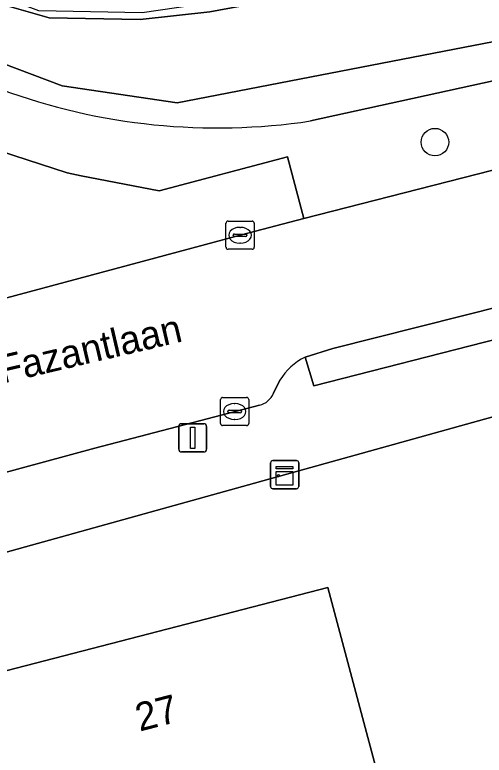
# Model space of a CAD drawing. Extents: x 161772 to 163126, y 383092 to 383917.
# Drawn here: x 161980.53 to 161997.2, y 383449.11 to 383475.41 of the extents above; entities that cross this region are included whole.
import ezdxf

# ---------------------------------------------------------------- set-up
doc = ezdxf.new("R2010")
doc.units = 0
for name, color, linetype in [('IMGEO_Boom', 7, 'Continuous'), ('IMGEO_Erf', 7, 'Continuous'), ('IMGEO_Groenvoorziening', 7, 'Continuous'), ('IMGEO_Kast', 7, 'Continuous'), ('IMGEO_Kolk', 7, 'Continuous'), ('IMGEO_Lichtmast', 7, 'Continuous'), ('IMGEO_Oever', 7, 'Continuous'), ('IMGEO_Openbare_ruimte_label', 7, 'Continuous'), ('IMGEO_Pand', 7, 'Continuous'), ('IMGEO_Pand_nummerreeks', 7, 'Continuous'), ('IMGEO_Rijbaan_lokaal_gesloten', 7, 'Continuous'), ('IMGEO_Voetpad_gesloten', 7, 'Continuous'), ('IMGEO_Voetpad_open', 7, 'Continuous'), ('IMGEO_Waterloop', 7, 'Continuous')]:
    doc.layers.add(name, color=color, linetype=linetype)

msp = doc.modelspace()

# ---------------------------------------------------------------- linework, layer by layer
at = {"layer": 'IMGEO_Boom'}
msp.add_circle((161995.452, 383470.891), 0.489, dxfattribs=at)
at = {"layer": 'IMGEO_Erf'}
msp.add_lwpolyline([(162013.474, 383465.049), (162000.265, 383462.051), (162000.295, 383461.907), (161996.785, 383460.931), (161992.404, 383459.714), (161973.318, 383454.411), (161972.09, 383452.564), (161979.364, 383425.078), (161979.14, 383425.031), (161985.923, 383398.52), (161987.571, 383390.708)], dxfattribs=at)
msp.add_lwpolyline([(161984.667, 383430.279), (161984.004, 383430.663), (161982.385, 383436.719), (161981.739, 383439.133), (161980.721, 383438.861), (161979.488, 383439.574), (161978.579, 383442.975), (161977.67, 383446.373), (161978.28, 383447.427), (161979.282, 383447.695), (161978.237, 383451.598), (161991.651, 383455.067), (161992.979, 383450.097), (161993.795, 383447.047), (161990.987, 383446.296), (161991.115, 383445.818), (161991.983, 383442.57), (161993.405, 383442.951), (161994.309, 383439.636), (161996.032, 383433.317), (161989.498, 383431.57)], close=True, dxfattribs=at)
at = {"layer": 'IMGEO_Groenvoorziening'}
for points in [[(162031.7, 383476.189), (162040.283, 383477.247), (162056.048, 383479.111), (162056.772, 383479.174), (162056.543, 383481.404), (162057.145, 383481.468), (162057.113, 383481.8), (162057.695, 383483.305), (162056.342, 383483.117), (162028.627, 383479.262), (162018.222, 383477.318), (162000, 383473.614), (161991.036, 383471.642)], [(161977.609, 383471.347), (161982.392, 383469.803), (161982.884, 383469.691), (161985.654, 383469.166), (161990.219, 383470.372), (161990.801, 383468.172), (162000, 383470.537), (162011.434, 383473.114)]]:
    msp.add_lwpolyline(points, dxfattribs=at)
msp.add_arc((161987.728, 383493.685), 22.29, 249.8312, 278.534, dxfattribs=at)
at = {"layer": 'IMGEO_Kast'}
for p, q in [((161989.69, 383459.579), (161990.531, 383459.579)), ((161990.531, 383459.579), (161989.69, 383459.579)), ((161989.615, 383458.654), (161989.615, 383459.495)), ((161989.615, 383459.495), (161989.615, 383458.654)), ((161990.615, 383459.504), (161990.615, 383458.663)), ((161990.615, 383458.663), (161990.615, 383459.504)), ((161990.54, 383458.579), (161989.699, 383458.579)), ((161989.699, 383458.579), (161990.54, 383458.579))]:
    msp.add_line(p, q, dxfattribs=at)
for points in [[(161989.81, 383459.369), (161990.41, 383459.369), (161990.41, 383459.284), (161989.81, 383459.284), (161989.81, 383459.369)], [(161989.81, 383459.194), (161990.41, 383459.194), (161990.41, 383458.705), (161989.81, 383458.705), (161989.81, 383459.194)]]:
    msp.add_lwpolyline(points, dxfattribs=at)
msp.add_circle((161989.894, 383459.043), 0.0377, dxfattribs=at)
for centre, start, end in [((161989.693, 383459.501), 92.4484, 184.2845), ((161989.693, 383459.501), 92.4484, 184.2845), ((161990.537, 383459.501), 2.4484, 94.2845), ((161990.537, 383459.501), 2.4484, 94.2845), ((161989.693, 383458.657), 182.4484, 274.2845), ((161989.693, 383458.657), 182.4484, 274.2845), ((161990.537, 383458.657), 272.4484, 4.2845), ((161990.537, 383458.657), 272.4484, 4.2845)]:
    msp.add_arc(centre, 0.0779, start, end, dxfattribs=at)
at = {"layer": 'IMGEO_Kolk'}
for p, q in [((161988.031, 383467.158), (161988.031, 383468.01)), ((161988.106, 383468.084), (161988.958, 383468.084)), ((161989.032, 383468.01), (161989.032, 383467.158)), ((161988.519, 383467.864), (161988.544, 383467.864)), ((161988.29, 383467.578), (161988.29, 383467.59)), ((161988.728, 383467.541), (161988.33, 383467.541)), ((161988.333, 383467.627), (161988.731, 383467.627)), ((161988.774, 383467.59), (161988.774, 383467.578)), ((161988.542, 383467.304), (161988.517, 383467.304)), ((161988.958, 383467.084), (161988.106, 383467.084)), ((161987.838, 383460.895), (161987.838, 383461.747)), ((161987.913, 383461.821), (161988.765, 383461.821)), ((161988.839, 383461.747), (161988.839, 383460.895)), ((161988.14, 383461.364), (161988.538, 383461.364)), ((161988.326, 383461.601), (161988.351, 383461.601)), ((161988.097, 383461.315), (161988.097, 383461.327)), ((161988.535, 383461.278), (161988.137, 383461.278)), ((161988.581, 383461.327), (161988.581, 383461.315)), ((161988.349, 383461.041), (161988.324, 383461.041)), ((161988.765, 383460.821), (161987.913, 383460.821))]:
    msp.add_line(p, q, dxfattribs=at)
for points in [[(161988.031, 383467.158), (161988.031, 383468.01)], [(161988.106, 383468.084), (161988.958, 383468.084)], [(161989.032, 383468.01), (161989.032, 383467.158)], [(161988.958, 383467.084), (161988.106, 383467.084)], [(161987.838, 383460.895), (161987.838, 383461.747)], [(161987.913, 383461.821), (161988.765, 383461.821)], [(161988.839, 383461.747), (161988.839, 383460.895)], [(161988.765, 383460.821), (161987.913, 383460.821)]]:
    msp.add_lwpolyline(points, dxfattribs=at)
for centre, radius, start, end in [((161988.108, 383468.008), 0.0765, 91.552, 178.448), ((161988.108, 383468.008), 0.0765, 91.552, 178.448), ((161988.956, 383468.008), 0.0765, 1.552, 88.448), ((161988.956, 383468.008), 0.0765, 1.552, 88.448), ((161988.33, 383467.587), 0.0403, 85.8775, 175.7526), ((161988.327, 383467.577), 0.0366, 178.938, 274.7102), ((161988.731, 383467.584), 0.043, 264.8664, 352.4533), ((161988.735, 383467.589), 0.0386, 1.7309, 96.639), ((161988.108, 383467.16), 0.0765, 181.552, 268.448), ((161988.108, 383467.16), 0.0765, 181.552, 268.448), ((161988.956, 383467.16), 0.0765, 271.552, 358.448), ((161988.956, 383467.16), 0.0765, 271.552, 358.448), ((161987.915, 383461.745), 0.0765, 91.552, 178.448), ((161987.915, 383461.745), 0.0765, 91.552, 178.448), ((161988.763, 383461.745), 0.0765, 1.552, 88.448), ((161988.763, 383461.745), 0.0765, 1.552, 88.448), ((161988.137, 383461.324), 0.0403, 85.8775, 175.7526), ((161988.542, 383461.326), 0.0386, 1.7309, 96.639), ((161988.134, 383461.314), 0.0366, 178.938, 274.7102), ((161988.538, 383461.321), 0.043, 264.8664, 352.4533), ((161987.915, 383460.897), 0.0765, 181.552, 268.448), ((161987.915, 383460.897), 0.0765, 181.552, 268.448), ((161988.763, 383460.897), 0.0765, 271.552, 358.448), ((161988.763, 383460.897), 0.0765, 271.552, 358.448)]:
    msp.add_arc(centre, radius, start, end, dxfattribs=at)
for centre, major_axis, ratio, start_param, end_param in [((161988.518, 383467.584), (-0.387, 0.002), 0.722429, 4.712389, 7.853982), ((161988.543, 383467.584), (-0.39, 0.002), 0.717154, 1.570796, 4.712389), ((161988.325, 383461.321), (-0.387, 0.002), 0.722429, 4.712389, 7.853982), ((161988.35, 383461.321), (-0.39, 0.002), 0.717154, 1.570796, 4.712389)]:
    msp.add_ellipse(centre, major_axis=major_axis, ratio=ratio, start_param=start_param, end_param=end_param, dxfattribs=at)
at = {"layer": 'IMGEO_Lichtmast'}
for p, q in [((161986.451, 383460.887), (161987.241, 383460.887)), ((161987.241, 383460.887), (161986.451, 383460.887)), ((161986.351, 383459.987), (161986.351, 383460.787)), ((161986.351, 383460.787), (161986.351, 383459.987)), ((161987.341, 383460.787), (161987.341, 383459.987)), ((161987.341, 383459.987), (161987.341, 383460.787)), ((161987.241, 383459.887), (161986.451, 383459.887)), ((161986.451, 383459.887), (161987.241, 383459.887))]:
    msp.add_line(p, q, dxfattribs=at)
msp.add_lwpolyline([(161986.771, 383460.762), (161986.921, 383460.762), (161986.921, 383460.012), (161986.771, 383460.012), (161986.771, 383460.762)], dxfattribs=at)
for centre, start, end in [((161986.451, 383460.787), 90, 180), ((161986.451, 383460.787), 90, 180), ((161987.241, 383460.787), 0, 90), ((161987.241, 383460.787), 360, 90), ((161986.451, 383459.987), 180, 270), ((161986.451, 383459.987), 180, 270), ((161987.241, 383459.987), 270, 0), ((161987.241, 383459.987), 270, 0)]:
    msp.add_arc(centre, 0.1, start, end, dxfattribs=at)
at = {"layer": 'IMGEO_Oever'}
for points in [[(161968.185, 383587.81), (161967.027, 383542.026), (161966.921, 383536.187), (161967.069, 383521.293), (161967.494, 383512.015), (161968.003, 383504.245), (161969.999, 383490.826), (161970.806, 383485.391), (161971.56, 383483.438), (161972.271, 383481.474), (161973.577, 383479.552), (161976.188, 383477.535), (161979.67, 383475.901), (161981.751, 383475.306), (161984.978, 383475.242), (161987.462, 383475.518), (162006.931, 383479.128)], [(162012.791, 383477.429), (161986.294, 383472.291), (161982.218, 383472.886), (161977.504, 383474.669), (161973.895, 383477.09), (161969.819, 383481.803), (161967.908, 383485.625), (161966.634, 383491.697), (161965.275, 383502.482), (161964.086, 383516.75), (161964.086, 383543.225), (161965.02, 383573.799)], [(161991.036, 383471.642), (162000, 383473.614), (162018.222, 383477.318), (162028.627, 383479.262), (162056.342, 383483.117), (162056.089, 383487.148), (162024.66, 383484.243), (162023.973, 383482.964), (162008.602, 383480.252), (162000, 383478.407), (161989.359, 383476.124), (161985.059, 383475.485), (161981.383, 383475.556), (161977.883, 383476.873), (161974.528, 383478.971), (161972.364, 383481.627), (161971.06, 383485.483), (161969.003, 383500), (161968.172, 383505.868)]]:
    msp.add_lwpolyline(points, dxfattribs=at)
msp.add_arc((161987.728, 383493.685), 22.29, 249.8312, 278.534, dxfattribs=at)
at = {"layer": 'IMGEO_Pand'}
msp.add_lwpolyline([(161992.979, 383450.097), (161991.651, 383455.067), (161978.237, 383451.598), (161979.282, 383447.695), (161978.28, 383447.427), (161977.67, 383446.373), (161978.579, 383442.975), (161990.987, 383446.296), (161993.795, 383447.047)], close=True, dxfattribs=at)
at = {"layer": 'IMGEO_Rijbaan_lokaal_gesloten'}
for points in [[(162011.434, 383473.114), (162000, 383470.537), (161990.801, 383468.172), (161988.586, 383467.602), (161974.762, 383463.893), (161976.061, 383459.406)], [(161990.842, 383463.254), (161991.825, 383463.563), (162004.039, 383466.644)], [(161989.716, 383461.969), (161989.949, 383462.434)], [(161978.957, 383458.822), (161983.369, 383460.024), (161989.219, 383461.551)]]:
    msp.add_lwpolyline(points, dxfattribs=at)
for centre, radius, start, end in [((161991.776, 383461.341), 2.129, 116.0176, 149.102), ((161989.084, 383462.217), 0.679, 281.5037, 338.6271)]:
    msp.add_arc(centre, radius, start, end, dxfattribs=at)
at = {"layer": 'IMGEO_Voetpad_gesloten'}
for points in [[(161988.586, 383467.602), (161990.801, 383468.172), (161990.219, 383470.372), (161985.654, 383469.166), (161982.884, 383469.691), (161982.392, 383469.803), (161977.609, 383471.347)], [(161973.234, 383463.506), (161974.762, 383463.893), (161988.586, 383467.602)]]:
    msp.add_lwpolyline(points, dxfattribs=at)
at = {"layer": 'IMGEO_Voetpad_open'}
msp.add_lwpolyline([(161990.842, 383463.254), (161991.155, 383462.23), (162004.29, 383465.591), (162004.039, 383466.644), (161991.825, 383463.563)], close=True, dxfattribs=at)
for points in [[(162004.039, 383466.644), (162004.29, 383465.591), (161991.155, 383462.23), (161990.842, 383463.254)], [(161989.949, 383462.434), (161989.716, 383461.969)], [(161970.936, 383457.241), (161972.09, 383452.564), (161973.318, 383454.411), (161992.404, 383459.714), (161996.785, 383460.931), (162000.295, 383461.907)], [(161989.219, 383461.551), (161983.369, 383460.024), (161978.957, 383458.822)]]:
    msp.add_lwpolyline(points, dxfattribs=at)
for centre, radius, start, end in [((161991.776, 383461.341), 2.129, 116.0176, 149.102), ((161989.084, 383462.217), 0.679, 281.5037, 338.6271)]:
    msp.add_arc(centre, radius, start, end, dxfattribs=at)
at = {"layer": 'IMGEO_Waterloop'}
for points in [[(162006.931, 383479.128), (161987.462, 383475.518), (161984.978, 383475.242), (161981.751, 383475.306), (161979.67, 383475.901), (161976.188, 383477.535), (161973.577, 383479.552), (161972.271, 383481.474), (161971.56, 383483.438), (161970.806, 383485.391), (161969.999, 383490.826), (161968.003, 383504.245), (161967.494, 383512.015), (161967.069, 383521.293), (161966.921, 383536.187), (161967.027, 383542.026), (161968.185, 383587.81)], [(161965.02, 383573.799), (161964.086, 383543.225), (161964.086, 383516.75), (161965.275, 383502.482), (161966.634, 383491.697), (161967.908, 383485.625), (161969.819, 383481.803), (161973.895, 383477.09), (161977.504, 383474.669), (161982.218, 383472.886), (161986.294, 383472.291), (162012.791, 383477.429)]]:
    msp.add_lwpolyline(points, dxfattribs=at)

# ---------------------------------------------------------------- texts
at = {"layer": 'IMGEO_Openbare_ruimte_label'}
msp.add_text('Fazantlaan', height=1, rotation=13.1749, dxfattribs=at).set_placement((161980.094, 383462.312))
at = {"layer": 'IMGEO_Pand_nummerreeks'}
msp.add_text('27', height=1, rotation=14.5016, dxfattribs=at).set_placement((161984.964, 383449.95))

doc.saveas('drawing.dxf')
